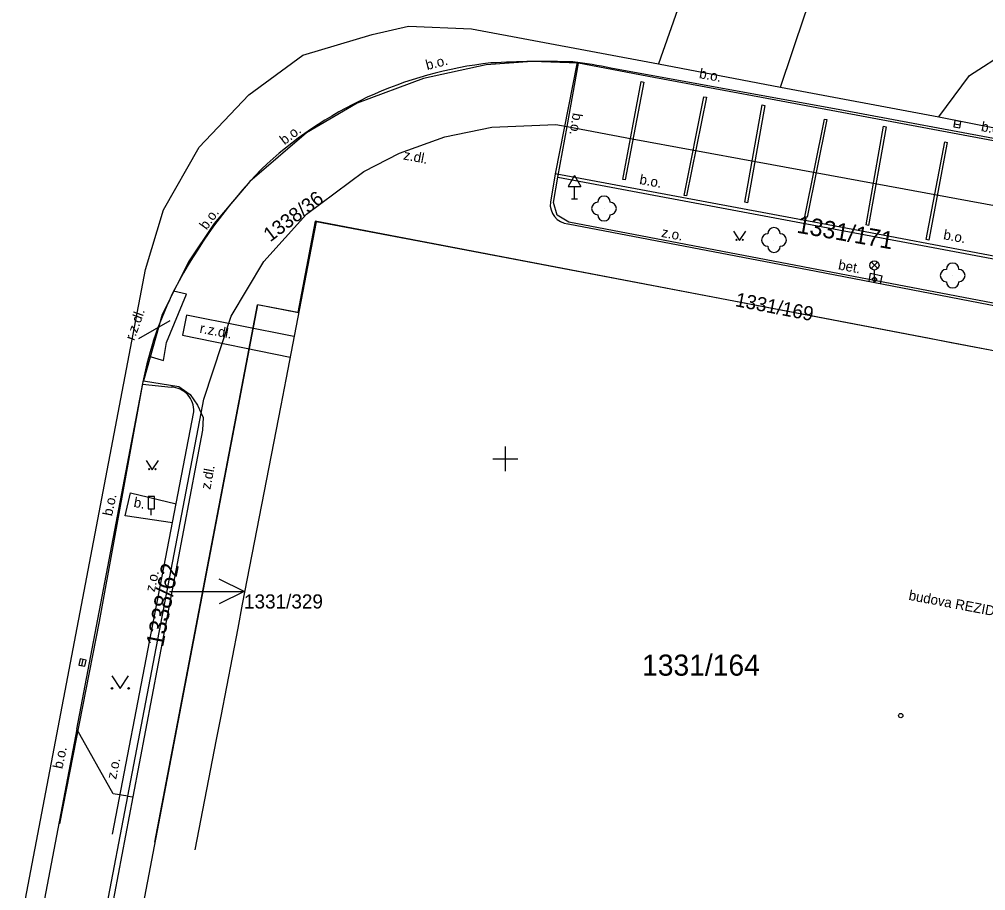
# Model space of a CAD drawing. Extents: x -601602 to -600882, y -1162594 to -1161950.
# Drawn here: x -601269.56 to -601230.67, y -1162117.38 to -1162082.3 of the extents above; entities that cross this region are included whole.
import ezdxf

# ---------------------------------------------------------------- set-up
doc = ezdxf.new("R2010")
doc.units = 0
for name, color, linetype in [('KN_Hranice parcel', 7, 'Continuous'), ('KN_Parcelní čísla', 7, 'Continuous'), ('KN_Pop  PČ popisy', 7, 'Continuous'), ('KN_Vnitřní kresba', 7, 'Continuous'), ('KN_Značky budov', 7, 'Continuous'), ('KN_Značky kultur', 7, 'Continuous'), ('Vrstva 14', 7, 'Continuous'), ('Vrstva 15', 7, 'Continuous'), ('Vrstva 19', 7, 'Continuous'), ('Vrstva 25', 7, 'Continuous'), ('Vrstva 29', 7, 'Continuous'), ('Vrstva 4', 7, 'Continuous'), ('Vrstva 49', 7, 'Continuous'), ('VRSTVA 5', 7, 'Continuous'), ('Vrstva 7', 7, 'Continuous'), ('X_SOUR_KRIZKY_SEVER', 7, 'Continuous')]:
    doc.layers.add(name, color=color, linetype=linetype)

# ---------------------------------------------------------------- blocks, each defined once
blk = doc.blocks.new('1029_62')
at = {"layer": 'KN_Pop  PČ popisy'}
for p, q in [((3.001, 0), (2, 0.501)), ((0, 0), (3.001, 0)), ((3.001, 0), (2, -0.501))]:
    blk.add_line(p, q, dxfattribs=at)

msp = doc.modelspace()

# ---------------------------------------------------------------- linework, layer by layer
at = {"layer": 'KN_Hranice parcel'}
for p, q in [((-601240.59, -1162074.86), (-601243.84, -1162084.09)), ((-601247.52, -1162086.62), (-601247.06, -1162084.07)), ((-601243.84, -1162084.09), (-601238.93, -1162085.03)), ((-601247.89, -1162088.66), (-601247.52, -1162086.62)), ((-601247.89, -1162088.66), (-601202.36, -1162097.2)), ((-601265.2, -1162113.58), (-601262.25, -1162098.16)), ((-601267.25, -1162110.88), (-601272.39, -1162137.77)), ((-601269.51, -1162136.12), (-601265.2, -1162113.58)), ((-601265.2, -1162113.58), (-601264.99, -1162113.61)), ((-601264.99, -1162113.61), (-601269.27, -1162136.18))]:
    msp.add_line(p, q, dxfattribs=at)
for points in [[(-601238.93, -1162085.03), (-601237.95, -1162082.12), (-601235.72, -1162076.14), (-601233.56, -1162071.26), (-601230.52, -1162065.27), (-601226.44, -1162058.84), (-601219, -1162048.28)], [(-601275.1, -1162151.83), (-601275.81, -1162151.7), (-601264.48, -1162092.37), (-601263.76, -1162089.98), (-601262.32, -1162087.45), (-601260.32, -1162085.35), (-601258.15, -1162083.75), (-601255.36, -1162082.92), (-601253.9, -1162082.58), (-601251.36, -1162082.69), (-601243.84, -1162084.09)], [(-601247.06, -1162084.07), (-601248.92, -1162084), (-601250.77, -1162084.14), (-601253.3, -1162084.68), (-601255.96, -1162085.68), (-601258, -1162086.87), (-601260.29, -1162088.83), (-601261.72, -1162090.53), (-601262.75, -1162092.07), (-601263.82, -1162094.19), (-601264.56, -1162096.86)], [(-601202.1, -1162095.83), (-601201.76, -1162093.97), (-601201.49, -1162092.55), (-601211.36, -1162090.74), (-601223.12, -1162088.55), (-601230.57, -1162087.16), (-601239.11, -1162085.56), (-601244.03, -1162084.64), (-601247.06, -1162084.07)], [(-601238.93, -1162085.03), (-601232.56, -1162086.23), (-601230.25, -1162086.69)], [(-601262.25, -1162098.16), (-601262.14, -1162097.6), (-601261.04, -1162094.26), (-601259.72, -1162092.06), (-601258.01, -1162090.15), (-601255.7, -1162088.43), (-601254.26, -1162087.69), (-601252.44, -1162087.03), (-601250.55, -1162086.64), (-601247.97, -1162086.54), (-601247.52, -1162086.62)], [(-601247.52, -1162086.62), (-601244.9, -1162087.11), (-601239.93, -1162088.03), (-601233.95, -1162089.13), (-601231.85, -1162089.52), (-601223.82, -1162091), (-601202.1, -1162095.83)], [(-601202.36, -1162097.2), (-601202.56, -1162098.21), (-601202.97, -1162098.77), (-601203.59, -1162098.85), (-601247.45, -1162090.47), (-601247.92, -1162090.19), (-601248.07, -1162089.68), (-601247.89, -1162088.66)], [(-601200.05, -1162101.62), (-601200.02, -1162101.45), (-601257.65, -1162090.43), (-601258.35, -1162094.11), (-601259.98, -1162093.8), (-601271.27, -1162152.93), (-601269.66, -1162153.24), (-601270.36, -1162156.92), (-601270.25, -1162156.94)], [(-601267.25, -1162110.88), (-601264.59, -1162096.97), (-601264.56, -1162096.86)], [(-601264.56, -1162096.86), (-601263.14, -1162097.09), (-601262.69, -1162097.41), (-601262.39, -1162097.84), (-601262.25, -1162098.16)], [(-601262.25, -1162098.16), (-601262.17, -1162098.33), (-601262.19, -1162098.85), (-601264.99, -1162113.61)], [(-601265.2, -1162113.58), (-601265.79, -1162113.49), (-601267.25, -1162110.88)]]:
    msp.add_lwpolyline(points, dxfattribs=at)
at = {"layer": 'KN_Vnitřní kresba'}
for p, q in [((-601231.32, -1162084.56), (-601228.09, -1162082.47)), ((-601232.56, -1162086.23), (-601231.32, -1162084.56))]:
    msp.add_line(p, q, dxfattribs=at)
at = {"layer": 'KN_Značky budov'}
msp.add_circle((-601234.086, -1162110.335), 0.0875, dxfattribs=at)
at = {"layer": 'KN_Značky kultur'}
for p, q in [((-601265.835, -1162108.737), (-601265.5, -1162109.24)), ((-601265.5, -1162109.24), (-601265.165, -1162108.737))]:
    msp.add_line(p, q, dxfattribs=at)
for centre in [(-601265.835, -1162109.24), (-601265.165, -1162109.24)]:
    msp.add_circle(centre, 0.0335, dxfattribs=at)
at = {"layer": 'Vrstva 14'}
for p, q in [((-601240.824, -1162090.836), (-601240.574, -1162091.21)), ((-601240.574, -1162091.21), (-601240.324, -1162090.836)), ((-601264.46, -1162100.062), (-601264.21, -1162100.436)), ((-601264.21, -1162100.436), (-601263.96, -1162100.062))]:
    msp.add_line(p, q, dxfattribs=at)
for points in [[(-601240.699, -1162091.211), (-601240.724, -1162091.186), (-601240.699, -1162091.161)], [(-601240.699, -1162091.211), (-601240.699, -1162091.161), (-601240.674, -1162091.186)], [(-601240.449, -1162091.211), (-601240.474, -1162091.186), (-601240.449, -1162091.161)], [(-601240.449, -1162091.211), (-601240.449, -1162091.161), (-601240.424, -1162091.186)], [(-601264.335, -1162100.437), (-601264.36, -1162100.412), (-601264.335, -1162100.387)], [(-601264.335, -1162100.437), (-601264.335, -1162100.387), (-601264.31, -1162100.412)], [(-601264.085, -1162100.437), (-601264.11, -1162100.412), (-601264.085, -1162100.387)], [(-601264.085, -1162100.437), (-601264.085, -1162100.387), (-601264.06, -1162100.412)]]:
    msp.add_lwpolyline(points, close=True, dxfattribs=at)
for centre in [(-601246.03, -1162089.92), (-601239.19, -1162091.19), (-601232, -1162092.62)]:
    msp.add_circle(centre, 0.00025, dxfattribs=at)
for centre, start, end in [((-601246.03, -1162089.67), 0, 180), ((-601246.28, -1162089.92), 90, 270), ((-601245.78, -1162089.92), 270, 90), ((-601246.03, -1162090.17), 180, 360), ((-601239.44, -1162091.19), 90, 270), ((-601239.19, -1162090.94), 0, 180), ((-601238.94, -1162091.19), 270, 90), ((-601239.19, -1162091.44), 180, 360), ((-601232, -1162092.37), 0, 180), ((-601232.25, -1162092.62), 90, 270), ((-601231.75, -1162092.62), 270, 90), ((-601232, -1162092.87), 180, 360)]:
    msp.add_arc(centre, 0.25, start, end, dxfattribs=at)
at = {"layer": 'Vrstva 15'}
for p, q in [((-601264.127, -1162101.517), (-601264.377, -1162101.517)), ((-601264.377, -1162101.517), (-601264.377, -1162102.017)), ((-601264.127, -1162102.017), (-601264.127, -1162101.517)), ((-601264.377, -1162102.017), (-601264.127, -1162102.017)), ((-601264.377, -1162102.017), (-601264.377, -1162102.017)), ((-601264.252, -1162102.267), (-601264.252, -1162102.017))]:
    msp.add_line(p, q, dxfattribs=at)
at = {"layer": 'Vrstva 19'}
for p, q in [((-601247.22, -1162088.597), (-601247.47, -1162089.03)), ((-601247.22, -1162088.597), (-601246.97, -1162089.03)), ((-601247.47, -1162089.03), (-601246.97, -1162089.03)), ((-601247.22, -1162089.53), (-601247.22, -1162089.03)), ((-601247.345, -1162089.53), (-601247.095, -1162089.53))]:
    msp.add_line(p, q, dxfattribs=at)
at = {"layer": 'Vrstva 25'}
for p, q in [((-601231.909, -1162086.383), (-601231.957, -1162086.629)), ((-601231.957, -1162086.629), (-601231.711, -1162086.677)), ((-601231.957, -1162086.629), (-601231.957, -1162086.629)), ((-601231.933, -1162086.506), (-601231.687, -1162086.554)), ((-601231.663, -1162086.431), (-601231.909, -1162086.383)), ((-601231.711, -1162086.677), (-601231.663, -1162086.431)), ((-601267.119, -1162108.053), (-601267.167, -1162108.299)), ((-601266.873, -1162108.101), (-601267.119, -1162108.053)), ((-601267.044, -1162108.323), (-601266.996, -1162108.077)), ((-601266.921, -1162108.347), (-601266.873, -1162108.101)), ((-601267.167, -1162108.299), (-601266.921, -1162108.347)), ((-601266.921, -1162108.347), (-601266.921, -1162108.347))]:
    msp.add_line(p, q, dxfattribs=at)
at = {"layer": 'Vrstva 29'}
for p, q in [((-601235.282, -1162092.339), (-601235.018, -1162092.075)), ((-601235.014, -1162092.338), (-601235.278, -1162092.073)), ((-601235.15, -1162092.67), (-601235.15, -1162092.395))]:
    msp.add_line(p, q, dxfattribs=at)
for points in [[(-601235.15, -1162092.87), (-601235.25, -1162092.77), (-601235.15, -1162092.67)], [(-601235.15, -1162092.87), (-601235.15, -1162092.67), (-601235.05, -1162092.77)]]:
    msp.add_lwpolyline(points, close=True, dxfattribs=at)
msp.add_circle((-601235.15, -1162092.208), 0.188, dxfattribs=at)
at = {"layer": 'Vrstva 4'}
for p, q in [((-601221.7, -1162097.302), (-601232.055, -1162095.322)), ((-601260.772, -1162106.809), (-601261.457, -1162110.361)), ((-601261.637, -1162111.294), (-601262.493, -1162115.733))]:
    msp.add_line(p, q, dxfattribs=at)
at = {"layer": 'VRSTVA 5'}
for p, q in [((-601232.055, -1162095.323), (-601232.936, -1162095.154)), ((-601260.588, -1162105.852), (-601260.772, -1162106.809)), ((-601261.457, -1162110.361), (-601261.637, -1162111.294))]:
    msp.add_line(p, q, dxfattribs=at)
at = {"layer": 'Vrstva 7'}
for p, q in [((-601247.112, -1162084.026), (-601247.99, -1162088.52)), ((-601236.39, -1162085.97), (-601245.75, -1162084.27)), ((-601224.25, -1162088.25), (-601236.39, -1162085.97)), ((-601247.99, -1162088.52), (-601248.19, -1162089.66)), ((-601237.01, -1162090.58), (-601247.99, -1162088.52)), ((-601257.62, -1162090.46), (-601258.843, -1162096.805)), ((-601253.5, -1162091.24), (-601257.62, -1162090.46)), ((-601247.48, -1162090.54), (-601237.49, -1162092.44)), ((-601224.75, -1162092.89), (-601237.01, -1162090.58)), ((-601237.77, -1162094.23), (-601253.5, -1162091.24)), ((-601237.49, -1162092.44), (-601224.88, -1162094.89)), ((-601235.365, -1162092.853), (-601235.3, -1162092.52)), ((-601235.3, -1162092.52), (-601234.84, -1162092.63)), ((-601234.901, -1162092.943), (-601234.84, -1162092.63)), ((-601262.83, -1162093.37), (-601263.352, -1162093.244)), ((-601263.64, -1162095.31), (-601262.83, -1162093.37)), ((-601259.98, -1162093.8), (-601264.109, -1162115.425)), ((-601264.109, -1162115.424), (-601259.98, -1162093.8)), ((-601258.325, -1162094.119), (-601259.98, -1162093.8)), ((-601258.325, -1162094.119), (-601259.98, -1162093.8)), ((-601263.501, -1162094.439), (-601264.761, -1162095.169)), ((-601262.84, -1162094.21), (-601263, -1162095.02)), ((-601258.509, -1162095.07), (-601262.84, -1162094.21)), ((-601232.936, -1162095.154), (-601237.77, -1162094.23)), ((-601263, -1162095.02), (-601258.668, -1162095.899)), ((-601263.76, -1162096.04), (-601263.64, -1162095.31)), ((-601264.35, -1162095.87), (-601263.76, -1162096.04)), ((-601258.843, -1162096.805), (-601259.044, -1162097.847)), ((-601264.59, -1162096.9), (-601266.35, -1162106.54)), ((-601264.606, -1162096.988), (-601263.45, -1162097.11)), ((-601259.044, -1162097.847), (-601260.588, -1162105.852)), ((-601264.24, -1162106.95), (-601262.54, -1162098.11)), ((-601265.3, -1162102.29), (-601265.09, -1162101.37)), ((-601265.09, -1162101.37), (-601263.252, -1162101.812)), ((-601263.4, -1162102.581), (-601265.3, -1162102.29)), ((-601266.35, -1162106.54), (-601267.952, -1162114.695)), ((-601265.808, -1162115.102), (-601264.24, -1162106.95))]:
    msp.add_line(p, q, dxfattribs=at)
for points in [[(-601244.431, -1162084.829), (-601245.181, -1162088.769), (-601245.279, -1162088.751), (-601244.529, -1162084.811)], [(-601241.911, -1162085.44), (-601242.711, -1162089.41), (-601242.809, -1162089.39), (-601242.009, -1162085.42)], [(-601239.561, -1162085.769), (-601240.261, -1162089.689), (-601240.359, -1162089.671), (-601239.659, -1162085.751)], [(-601237.061, -1162086.34), (-601237.851, -1162090.27), (-601237.949, -1162090.25), (-601237.159, -1162086.32)], [(-601234.681, -1162086.629), (-601235.381, -1162090.599), (-601235.479, -1162090.581), (-601234.779, -1162086.611)], [(-601232.221, -1162087.259), (-601232.961, -1162091.189), (-601233.059, -1162091.171), (-601232.319, -1162087.241)]]:
    msp.add_lwpolyline(points, close=True, dxfattribs=at)
for centre, radius, start, end in [((-601248.493, -1162120.064), 36.064, 88.072, 93.3169), ((-601249.185, -1162100.487), 16.577, 78.0398, 83.4001), ((-601248.864, -1162099.877), 15.91, 96.1919, 133.5703), ((-601244.786, -1162102.898), 20.928, 135.96, 152.2691), ((-601247.394, -1162089.744), 0.801, 173.9839, 263.8105), ((-601250.436, -1162099.655), 14.419, 153.2281, 168.9853), ((-601263.483, -1162098.054), 0.944, 356.5795, 88.0249)]:
    msp.add_arc(centre, radius, start, end, dxfattribs=at)
at = {"layer": 'X_SOUR_KRIZKY_SEVER'}
for p, q in [((-601250, -1162100.5), (-601250, -1162099.5)), ((-601250.5, -1162100), (-601249.5, -1162100))]:
    msp.add_line(p, q, dxfattribs=at)

# ---------------------------------------------------------------- block references
at = {"layer": 'KN_Pop  PČ popisy'}
msp.add_blockref('1029_62', (-601263.52, -1162105.34), dxfattribs=at)

# ---------------------------------------------------------------- texts
at = {"layer": 'KN_Parcelní čísla'}
for s, height, rotation, p in [('1338/36', 0.57, 37, (-601259.466, -1162091.285)), ('1331/171', 0.7, 350, (-601238.301, -1162090.889)), ('1331/169', 0.5695, 349, (-601240.778, -1162093.849)), ('1338/62', 0.7, 79, (-601263.782, -1162107.603))]:
    msp.add_text(s, height=height, rotation=rotation, dxfattribs=at).set_placement(p)
for s, height, p in [('1331/329', 0.5695, (-601260.52, -1162106.024)), ('1331/164', 0.85, (-601244.5, -1162108.728))]:
    msp.add_text(s, height=height, dxfattribs=at).set_placement(p)
at = {"layer": 'Vrstva 49'}
for s, rotation, p in [('b.o.', 14.5281, (-601253.149, -1162084.348)), ('bet.', 349.2301, (-601236.626, -1162092.369)), ('z.o.', 78.2648, (-601264.114, -1162105.375)), ('budova REZIDENCE B', 349.2315, (-601233.791, -1162105.672)), ('b.o.', 78.2648, (-601267.828, -1162112.502)), ('z.o.', 78.2648, (-601265.668, -1162112.919))]:
    msp.add_text(s, height=0.4, rotation=rotation, dxfattribs=at).set_placement(p)
at = {"layer": 'Vrstva 7'}
for s, rotation, p in [('b.o.', 349.4716, (-601242.222, -1162084.665)), ('b.o.', 261.0236, (-601247.283, -1162086.057)), ('b.o.', 37.1685, (-601258.892, -1162087.373)), ('b.o.', 349.4716, (-601230.875, -1162086.797)), ('z.dl.', 349.2301, (-601254.128, -1162087.943)), ('b.o.', 349.4716, (-601244.626, -1162088.929)), ('b.o.', 54.1901, (-601262.025, -1162090.805)), ('z.o.', 349.4716, (-601243.743, -1162091.059)), ('b.o.', 349.4716, (-601232.394, -1162091.155)), ('r.z.dl.', 70.4456, (-601264.941, -1162095.262)), ('r.z.dl.', 349.2301, (-601262.326, -1162094.918)), ('z.dl.', 79.2301, (-601261.876, -1162101.251)), ('b.o.', 78.2648, (-601265.829, -1162102.324)), ('b.', 349.4716, (-601264.982, -1162101.931))]:
    msp.add_text(s, height=0.4, rotation=rotation, dxfattribs=at).set_placement(p)

doc.saveas('drawing.dxf')
